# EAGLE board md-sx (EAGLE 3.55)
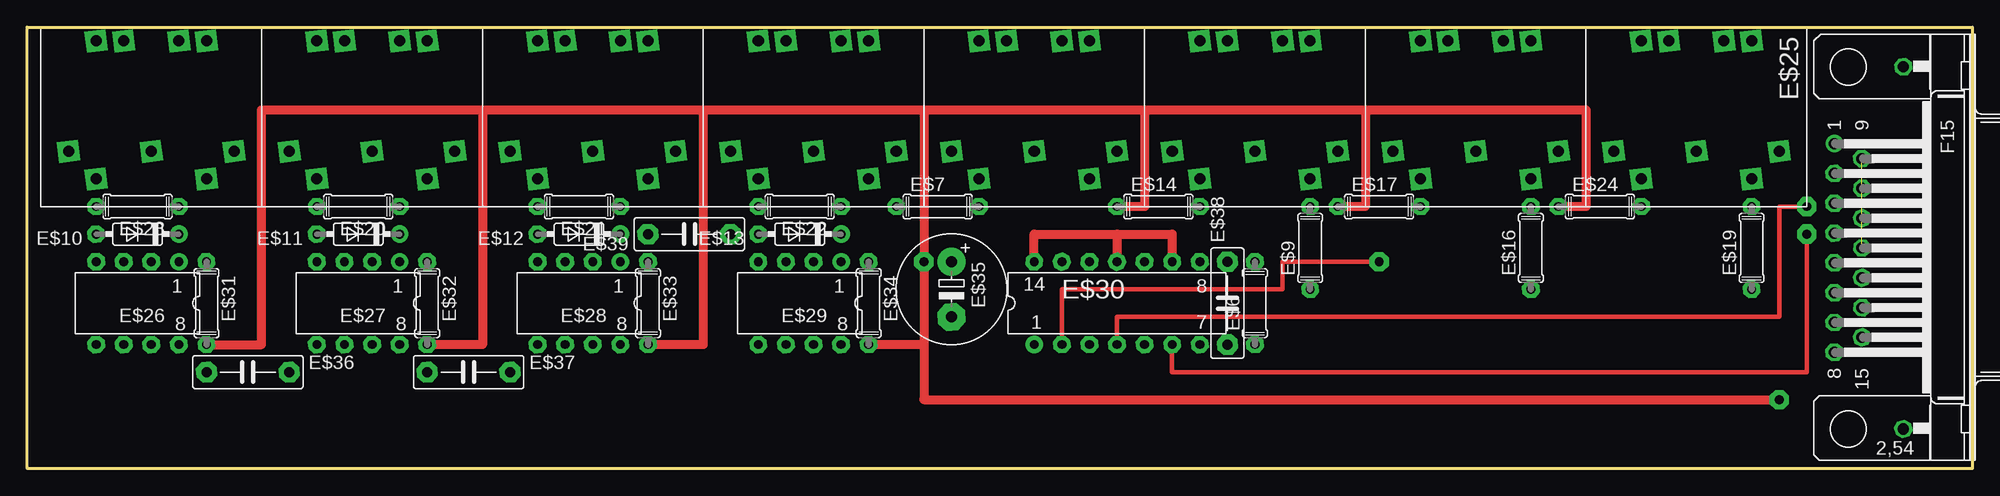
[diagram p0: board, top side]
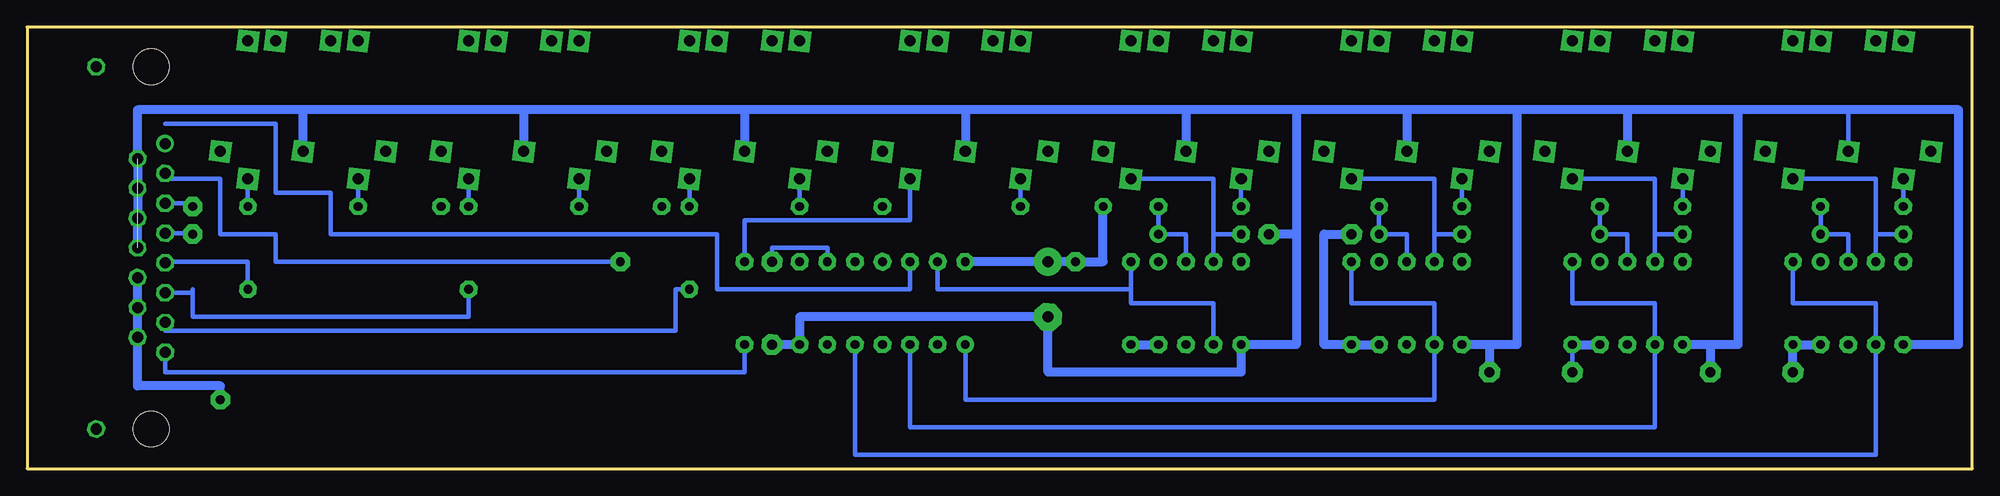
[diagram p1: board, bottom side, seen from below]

Size 179.07 x 40.64 mm. Coordinates in mm from the lower left corner, seen from the top.
Outline: 0,40.64 179.07,40.64 179.07,0 0,0 0,40.64
Copper layers used: Top, Bottom

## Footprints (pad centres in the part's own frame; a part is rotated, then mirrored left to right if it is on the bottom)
_PCB = drill 1.016 pad 1.93 square:  -7.62,10.16;  -5.08,10.16;  0,10.16;  2.54,10.16;  -2.54,0;  -7.62,-2.54;  -10.16,0;  2.54,-2.54;  5.08,0
07/7 = drill 0.813 pad 1.6 octagon:  -3.81,0;  3.81,0
35-7 = drill 0.813 pad 1.6 round:  -3.81,0 | drill 0.813 pad 1.6 octagon:  3.81,0
5H = drill 1.016 pad 1.6 round:  -9.601,-1.27 | drill 1.016 pad 1.6 octagon:  -6.858,-1.27;  -4.115,-1.27;  -1.372,-1.27;  1.372,-1.27;  4.115,-1.27;  6.858,-1.27;  9.601,-1.27;  -8.23,1.27;  -5.486,1.27;  -2.743,1.27;  0,1.27;  2.743,1.27;  5.486,1.27;  8.23,1.27;  -16.662,5.08;  16.662,5.08 | hole 3.302: -16.662,0; 16.662,0
L08 = drill 0.813 pad 1.6 round:  -3.81,-3.81 | drill 0.813 pad 1.6 octagon:  -1.27,-3.81;  1.27,-3.81;  3.81,-3.81;  3.81,3.81;  1.27,3.81;  -1.27,3.81;  -3.81,3.81
L14 = drill 0.813 pad 1.6 round:  -7.62,-3.81 | drill 0.813 pad 1.6 octagon:  -5.08,-3.81;  -2.54,-3.81;  0,-3.81;  2.54,-3.81;  5.08,-3.81;  7.62,-3.81;  7.62,3.81;  5.08,3.81;  2.54,3.81;  0,3.81;  -2.54,3.81;  -5.08,3.81;  -7.62,3.81
-10,5 = drill 1.016 pad 2.54 round:  -2.54,0 | drill 1.016 pad 2.54 octagon:  2.54,0
,5B3 = drill 0.914 pad 1.905 octagon:  -3.81,0;  3.81,0

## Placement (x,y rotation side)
E$1  [_PCB]  13.97,29.21 0 top
E$2  [_PCB]  34.29,29.21 0 top
E$3  [_PCB]  54.61,29.21 0 top
E$4  [_PCB]  74.93,29.21 0 top
E$5  [_PCB]  95.25,29.21 0 top
E$6  220  [07/7]  113.03,15.24 90 top
E$7  220  [07/7]  83.82,24.13 0 top
E$8  [_PCB]  115.57,29.21 0 top
E$9  220  [07/7]  118.11,20.32 90 top
E$10  1N4148  [35-7]  10.16,21.59 180 top
E$11  1N4148  [35-7]  30.48,21.59 180 top
E$12  1N4148  [35-7]  50.8,21.59 180 top
E$13  1N4148  [35-7]  71.12,21.59 180 top
E$14  220  [07/7]  104.14,24.13 0 top
E$15  [_PCB]  135.89,29.21 0 top
E$16  220  [07/7]  138.43,20.32 90 top
E$17  220  [07/7]  124.46,24.13 0 top
E$18  [_PCB]  156.21,29.21 0 top
E$19  220  [07/7]  158.75,20.32 90 top
E$20  220  [07/7]  30.48,24.13 180 top
E$21  220  [07/7]  50.8,24.13 180 top
E$22  220  [07/7]  71.12,24.13 180 top
E$23  220  [07/7]  10.16,24.13 180 top
E$24  220  [07/7]  144.78,24.13 0 top
E$25  [5H]  167.64,20.32 270 top
E$26  6N137  [L08]  10.16,15.24 180 top
E$27  6N137  [L08]  30.48,15.24 180 top
E$28  6N137  [L08]  50.8,15.24 180 top
E$29  6N137  [L08]  71.12,15.24 180 top
E$30  74HC14  [L14]  100.33,15.24 0 top
E$31  360  [07/7]  16.51,15.24 270 top
E$32  360  [07/7]  36.83,15.24 270 top
E$33  360  [07/7]  57.15,15.24 270 top
E$34  360  [07/7]  77.47,15.24 270 top
E$35  1000u/16V  [-10,5]  85.09,16.51 270 top
E$36  0.1  [,5B3]  20.32,8.89 0 top
E$37  0.1  [,5B3]  40.64,8.89 0 top
E$38  0.1  [,5B3]  110.49,15.24 90 top
E$39  0.1  [,5B3]  60.96,21.59 180 top

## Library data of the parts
E$1-E$5 E$8 E$15 E$18 = con-din
E$6 E$7 E$9 E$14 E$16 E$17 E$19-E$24 E$31-E$34 = r
E$10-E$13 = DIODE
E$25 = SUBD-A
E$26-E$29 = OPTOCPL
E$30 = 40XX
E$35 = POLCAP
E$36-E$39 = CAP

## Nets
S$1: E$5. E$7.
S$2: E$5. E$6.
S$3: E$8. E$14.
S$4: E$8. E$9.
S$5: E$15. E$17.
S$6: E$15. E$16.
S$7: E$18. E$24.
S$8: E$18. E$19.
S$9: E$25. E$30.
S$10: E$1. E$2. E$3. E$4. E$5. E$8. E$15. E$18. E$25. E$26. E$27. E$28. E$29. E$30. E$35. E$36. E$37. E$38. E$39.
S$11: E$25. E$30.
S$12: E$6. E$25.
S$13: E$10. E$23. E$26.
S$14: E$1. E$10. E$26.
S$15: E$2. E$11. E$27.
S$16: E$7. E$14. E$17. E$24. E$25. E$26. E$27. E$28. E$29. E$30. E$31. E$32. E$33. E$34. E$35. E$36. E$37. E$38. E$39.
S$17: E$25. E$30.
S$18: E$11. E$20. E$27.
S$20: E$2. E$20.
S$21: E$12. E$21. E$28.
S$22: E$1. E$23.
S$23: E$3. E$12. E$28.
S$24: E$3. E$21.
S$25: E$4. E$13. E$29.
S$26: E$4. E$22.
S$27: E$13. E$22. E$29.
S$30: E$26. E$30. E$31.
S$31: E$9. E$25.
S$33: E$27. E$30. E$32.
S$36: E$28. E$30. E$33.
S$37: E$29. E$30. E$34.
S$40: E$19. E$25.
S$41: E$16. E$25.
S$42: E$30.

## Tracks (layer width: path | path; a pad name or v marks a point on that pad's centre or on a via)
S$1
  Bottom 0.406: E$7. 87.63,26.67
S$2
  Bottom 0.406: E$6. 113.03,22.86 97.79,22.86 97.79,26.67
S$3
  Bottom 0.406: E$14. 107.95,26.67
S$4
  Bottom 0.406: E$9. 118.11,26.67
S$5
  Bottom 0.406: E$17. 128.27,26.67
S$6
  Bottom 0.406: E$16. 138.43,26.67
S$7
  Bottom 0.406: E$24. 148.59,26.67
S$8
  Bottom 0.406: E$19. 158.75,26.67
S$9  (via drill 0.81 pad 1.78)
  Top 0.406: v163.83,24.13 161.29,24.13 161.29,13.97 100.33,13.97 100.33,11.43
  Bottom 0.406: 166.37,24.43 163.83,24.43 v163.83,24.13
S$10  (4 unrouted)
  Bottom 0.406: 11.43,33.02 11.43,29.21
  Bottom 0.813: 110.49,11.43 107.95,11.43 107.95,13.97 E$35. 85.09,8.89 67.31,8.89 67.31,11.43 62.23,11.43 62.23,21.59 | 133.35,33.02 133.35,29.21 | 133.35,33.02 153.67,33.02 | 113.03,33.02 113.03,29.21 | 113.03,33.02 133.35,33.02 | 92.71,33.02 92.71,29.21 | 92.71,33.02 113.03,33.02 | 62.23,21.59 64.77,21.59 | 72.39,33.02 72.39,29.21 | 72.39,33.02 92.71,33.02 | 62.23,33.02 72.39,33.02 | 62.23,33.02 62.23,21.59 | 44.45,11.43 46.99,11.43 | 44.45,11.43 E$37. | 44.45,11.43 41.91,11.43 41.91,33.02 | 52.07,33.02 52.07,29.21 | 52.07,33.02 62.23,33.02 | 41.91,33.02 52.07,33.02 | 24.13,11.43 26.67,11.43 | 24.13,11.43 E$36. | 24.13,11.43 21.59,11.43 21.59,33.02 | 31.75,33.02 31.75,29.21 | 31.75,33.02 41.91,33.02 | 21.59,33.02 31.75,33.02 | 21.59,33.02 11.43,33.02 1.27,33.02 1.27,11.43 6.35,11.43 | 153.67,29.21 153.67,33.02 | 153.67,33.02 168.91,33.02 168.91,28.55 168.91,25.81 | 168.91,25.4 168.91,25.81 | 168.91,25.81 168.91,23.06 168.91,22.86 168.91,20.32
S$11  (via drill 0.81 pad 1.78)
  Top 0.406: v163.83,21.59 163.83,8.89 105.41,8.89 105.41,11.43
  Bottom 0.406: 166.37,21.69 163.83,21.69 v163.83,21.59
S$12
  Bottom 0.406: 113.03,11.43 113.03,8.89 166.37,8.89 166.37,10.72
S$13
  Bottom 0.406: 13.97,24.13 13.97,21.59 11.43,21.59 11.43,19.05
S$14
  Bottom 0.406: 8.89,21.59 E$10. | 8.89,19.05 8.89,21.59 | 8.89,21.59 8.89,26.67 16.51,26.67
S$15
  Bottom 0.406: 29.21,21.59 E$11. | 29.21,19.05 29.21,21.59 | 29.21,21.59 29.21,26.67 36.83,26.67
S$16  (via drill 0.81 pad 1.78)
  Top 0.813: 105.41,19.05 105.41,21.59 100.33,21.59 | 100.33,21.59 100.33,19.05 | 100.33,21.59 92.71,21.59 E$30. | 140.97,24.13 143.51,24.13 143.51,33.02 123.19,33.02 | 120.65,24.13 123.19,24.13 123.19,33.02 | v161.29,6.35 82.55,6.35 82.55,11.43 | 100.33,24.13 102.87,24.13 102.87,33.02 | 102.87,33.02 123.19,33.02 | 82.55,11.43 E$34. | 82.55,33.02 v82.55,19.05 82.55,11.43 | 82.55,33.02 102.87,33.02 | E$33. 62.23,11.43 62.23,33.02 | 62.23,33.02 82.55,33.02 | E$32. 41.91,11.43 41.91,33.02 | 41.91,33.02 62.23,33.02 | 41.91,33.02 21.59,33.02 21.59,11.43 E$31.
  Bottom 0.406: 168.91,15.24 168.91,14.83 | 168.91,12.7 168.91,12.09 | E$32. 36.83,8.89 | 105.41,19.05 105.41,20.32 110.49,20.32 E$38.
  Bottom 0.813: E$30. 85.09,19.05 v82.55,19.05 80.01,19.05 80.01,24.13 | 168.91,17.58 168.91,15.24 168.91,12.7 168.91,7.62 161.29,7.62 v161.29,6.35 | E$34. E$29. | E$28. E$33. 59.69,11.43 59.69,21.59 E$39. | E$32. E$27. | E$26. E$31. 16.51,8.89
S$17  (via drill 0.81 pad 1.78)
  Top 0.406: 95.25,11.43 95.25,16.51 115.57,16.51 115.57,19.05 v124.46,19.05
  Bottom 0.406: v124.46,19.05 156.21,19.05 156.21,21.59 161.29,21.59 161.29,26.67 166.37,26.67 166.37,27.18
S$18
  Bottom 0.406: 34.29,24.13 34.29,21.59 31.75,21.59 31.75,19.05
S$20
  Bottom 0.406: E$20. 26.67,26.67
S$21
  Bottom 0.406: 54.61,24.13 54.61,21.59 52.07,21.59 52.07,19.05
S$22
  Bottom 0.406: E$23. 6.35,26.67
S$23
  Bottom 0.406: 49.53,21.59 E$12. | 49.53,19.05 49.53,21.59 | 49.53,21.59 49.53,26.67 57.15,26.67
S$24
  Bottom 0.406: E$21. 46.99,26.67
S$25
  Bottom 0.406: 69.85,21.59 E$13. | 69.85,19.05 69.85,21.59 | 77.47,26.67 69.85,26.67 69.85,21.59
S$26
  Bottom 0.406: E$22. 67.31,26.67
S$27
  Bottom 0.406: 74.93,24.13 74.93,21.59 72.39,21.59 72.39,19.05
S$30
  Bottom 0.406: 16.51,19.05 16.51,15.24 8.89,15.24 8.89,11.43 8.89,1.27 102.87,1.27 102.87,11.43
S$31
  Bottom 0.406: 166.37,13.46 166.37,12.7 119.38,12.7 119.38,16.51 118.11,16.51
S$33
  Bottom 0.406: 36.83,19.05 36.83,15.24 29.21,15.24 29.21,11.43 29.21,3.81 97.79,3.81 97.79,11.43
S$36
  Bottom 0.406: 57.15,19.05 57.15,15.24 49.53,15.24 49.53,11.43 49.53,6.35 92.71,6.35 92.71,11.43
S$37
  Bottom 0.406: 77.47,16.51 77.47,19.05 | 77.47,16.51 77.47,15.24 69.85,15.24 69.85,11.43 | 77.47,16.51 95.25,16.51 95.25,19.05
S$40
  Bottom 0.406: 158.75,16.51 158.75,19.05 166.37,19.05 166.37,18.95
S$41
  Bottom 0.406: 166.37,16.21 163.83,16.21 | 163.83,16.21 163.83,16.51 | 163.83,16.21 163.83,13.97 138.43,13.97 138.43,16.51
S$42
  Bottom 0.406: 97.79,19.05 97.79,16.51 115.57,16.51 115.57,21.59 151.13,21.59 151.13,25.4 156.21,25.4 156.21,31.75 166.37,31.75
